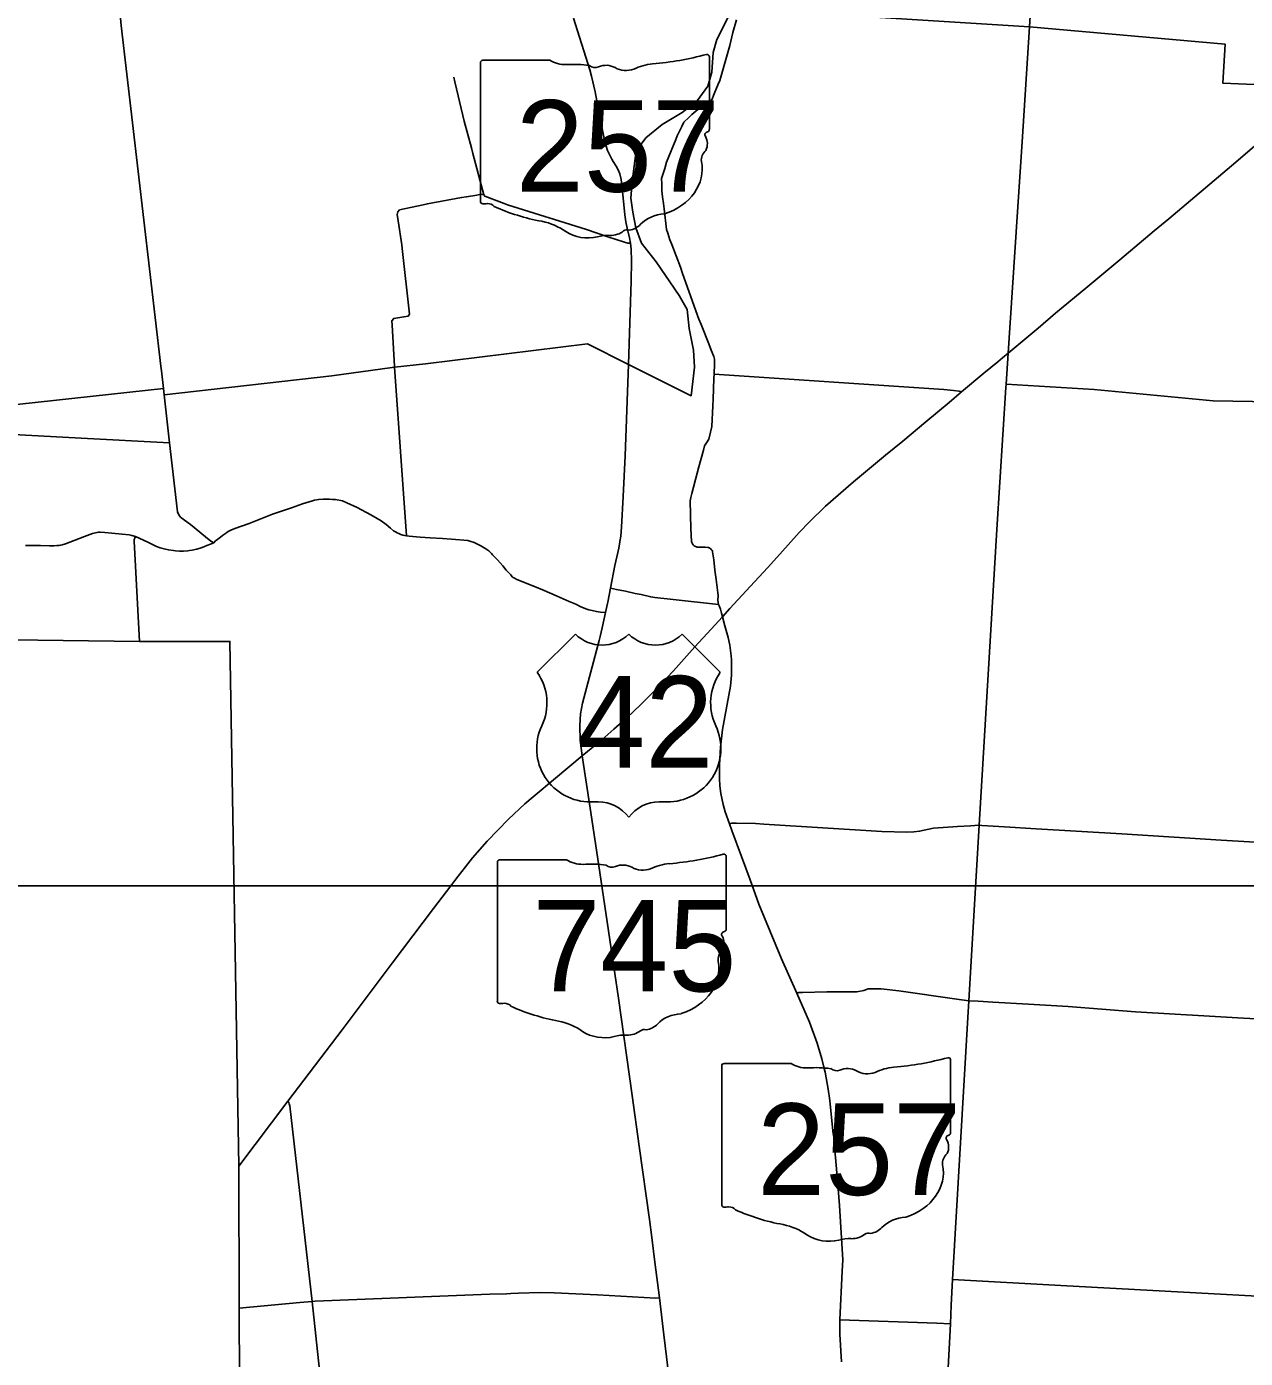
# Model space of a CAD drawing. Extents: x 1729596 to 1925846, y 659247 to 911751.
# Drawn here: x 1777664 to 1796200, y 807237 to 827504 of the extents above; entities that cross this region are included whole.
import ezdxf

# ---------------------------------------------------------------- set-up
doc = ezdxf.new("R2010")
doc.units = 0
for name, color, linetype in [('GM_X_County', 7, 'Continuous'), ('GM_X_County_Road', 7, 'Continuous'), ('GM_X_State_Route', 7, 'Continuous'), ('GM_X_State_Shield', 7, 'Continuous'), ('GM_X_Township', 7, 'Continuous'), ('GM_X_Township_Road', 7, 'Continuous'), ('GM_X_US_Route', 7, 'Continuous'), ('GM_X_US_Shield', 7, 'Continuous'), ('SH_Data', 7, 'Continuous')]:
    doc.layers.add(name, color=color, linetype=linetype)

msp = doc.modelspace()

# ---------------------------------------------------------------- linework, layer by layer
at = {"layer": 'GM_X_County'}
msp.add_lwpolyline([(1780927, 801312), (1780895, 808002), (1780889, 810163), (1780755, 818148), (1779378, 818146), (1775121, 818204)], dxfattribs=at)
at = {"layer": 'GM_X_County_Road'}
for points in [[(1792915, 827504), (1793116, 830642)], [(1792590, 822534), (1792728, 824607), (1792805, 825753), (1792915, 827502), (1792915, 827504)], [(1792558, 822011), (1792562, 822063), (1792590, 822534)], [(1791713, 807764), (1791713, 807764), (1791727, 808049), (1791747, 808435), (1791981, 812422), (1791996, 812680), (1792152, 815352), (1792421, 819851), (1792558, 822011)], [(1780612, 819735), (1780645, 819759), (1780686, 819790), (1780715, 819811), (1780738, 819826), (1780769, 819841), (1780828, 819865), (1781050, 819944), (1781402, 820082), (1781691, 820183), (1781861, 820241), (1782011, 820288), (1782042, 820296), (1782107, 820308), (1782172, 820313), (1782226, 820314), (1782272, 820313), (1782317, 820310), (1782363, 820305), (1782467, 820289), (1782536, 820259), (1782689, 820187), (1782899, 820076), (1782997, 820018), (1783056, 819981), (1783133, 819925), (1783197, 819870), (1783245, 819831), (1783272, 819816), (1783299, 819801), (1783327, 819788), (1783356, 819777), (1783385, 819767), (1783414, 819758), (1783439, 819754), (1783481, 819748), (1783650, 819735), (1783803, 819726), (1783988, 819713), (1784127, 819703), (1784372, 819682), (1784405, 819673), (1784469, 819651), (1784531, 819623), (1784574, 819600), (1784624, 819574), (1784647, 819559), (1784692, 819525), (1784732, 819486), (1784749, 819467), (1784825, 819388), (1784904, 819298), (1784959, 819231), (1785026, 819159), (1785050, 819133), (1785064, 819122), (1785094, 819104), (1785110, 819097), (1785248, 819040), (1785388, 818983), (1785533, 818924), (1785732, 818836), (1785914, 818757), (1786015, 818713), (1786091, 818676), (1786184, 818639), (1786216, 818628), (1786266, 818617), (1786329, 818603), (1786391, 818595), (1786468, 818586)], [(1777646, 819609), (1777873, 819605), (1778013, 819603), (1778079, 819603), (1778121, 819605), (1778161, 819608), (1778180, 819612), (1778205, 819618), (1778254, 819633), (1778388, 819686), (1778546, 819745), (1778668, 819790), (1778690, 819797), (1778713, 819802), (1778736, 819806), (1778759, 819808), (1778782, 819808), (1778853, 819805), (1778958, 819793), (1779119, 819779), (1779223, 819769), (1779266, 819761), (1779322, 819743), (1779440, 819691), (1779516, 819654)], [(1779516, 819654), (1779548, 819638), (1779641, 819594), (1779696, 819573), (1779754, 819555), (1779819, 819540), (1779897, 819529), (1779930, 819524), (1779991, 819521), (1780049, 819522), (1780114, 819528), (1780141, 819532), (1780183, 819537), (1780250, 819552), (1780319, 819573), (1780359, 819588), (1780402, 819606), (1780462, 819630), (1780509, 819649), (1780536, 819678), (1780571, 819703), (1780612, 819735)], [(1786546, 818956), (1786635, 818936), (1786770, 818912), (1786920, 818877), (1787011, 818860), (1787156, 818825), (1787219, 818816), (1787498, 818787), (1787499, 818787)], [(1787499, 818787), (1788188, 818712), (1788200, 818681), (1788215, 818640), (1788230, 818576), (1788246, 818524)], [(1782890, 800490), (1782881, 800644), (1782856, 800863), (1782676, 802437), (1782464, 804119), (1782395, 804661), (1782246, 805871), (1782006, 808105), (1781669, 811078), (1781659, 811109), (1781650, 811131), (1781636, 811151)], [(1791747, 808435), (1793395, 808348), (1794980, 808260), (1797031, 808146), (1797107, 808141), (1797153, 808138)], [(1780895, 808002), (1781819, 808088), (1782006, 808105), (1782052, 808109), (1784707, 808216), (1784962, 808220), (1785026, 808223), (1785143, 808231), (1785474, 808240), (1785685, 808234), (1786347, 808204), (1787231, 808155), (1787289, 808159)], [(1790033, 807825), (1791509, 807773), (1791713, 807764)], [(1791328, 800949), (1791359, 801588), (1791381, 801980), (1791400, 802336), (1791517, 804248), (1791555, 804839), (1791576, 805255), (1791663, 806861), (1791666, 806898), (1791673, 806996), (1791713, 807764)]]:
    msp.add_lwpolyline(points, dxfattribs=at)
at = {"layer": 'GM_X_State_Route'}
for points in [[(1786687, 819666), (1786699, 819749), (1786713, 819884), (1786736, 820353), (1786769, 820971), (1786817, 822362), (1786859, 823630), (1786863, 823932), (1786858, 824119), (1786848, 824207), (1786835, 824290), (1786796, 824437), (1786775, 824531), (1786760, 824638), (1786736, 824900), (1786705, 825179), (1786684, 825266), (1786661, 825325), (1786630, 825381), (1786584, 825450), (1786562, 825489), (1786529, 825557), (1786500, 825620), (1786459, 825751), (1786384, 826129), (1786309, 826513), (1786256, 826749), (1786229, 826847), (1785980, 827630)], [(1786502, 818744), (1786546, 818956), (1786609, 819304), (1786669, 819567), (1786687, 819663), (1786687, 819666)], [(1786385, 818223), (1786418, 818357), (1786468, 818586), (1786499, 818725), (1786502, 818744)], [(1788344, 817330), (1788369, 817465), (1788384, 817635), (1788386, 817682), (1788383, 817868), (1788379, 817929), (1788358, 818089), (1788333, 818205), (1788285, 818386), (1788246, 818524)], [(1786113, 816405), (1786081, 816641), (1786075, 816867), (1786090, 817045), (1786116, 817206), (1786370, 818161), (1786385, 818223)], [(1789933, 810648), (1789882, 811163), (1789857, 811335), (1789809, 811591), (1789782, 811691), (1789760, 811794), (1789687, 812036), (1789570, 812353), (1789380, 812793), (1789145, 813319), (1788800, 814150), (1788666, 814519), (1788535, 814873), (1788387, 815268), (1788352, 815370), (1788288, 815554), (1788258, 815665), (1788224, 815834), (1788209, 815948), (1788201, 816063), (1788201, 816122), (1788200, 816272), (1788218, 816541), (1788249, 816808), (1788344, 817330)], [(1787451, 806800), (1787357, 807594), (1787289, 808159), (1787220, 808700), (1787174, 809078), (1787137, 809350), (1786980, 810466), (1786873, 811238), (1786667, 812717), (1786361, 814768), (1786233, 815611), (1786113, 816405)], [(1789995, 809943), (1789934, 810642), (1789933, 810648)], [(1790058, 807184), (1790033, 807604), (1790033, 807825), (1790068, 808566), (1790079, 808738), (1790028, 809565), (1789995, 809943)]]:
    msp.add_lwpolyline(points, dxfattribs=at)
at = {"layer": 'GM_X_State_Shield'}
for p, q in [((1784567, 826956), (1784567, 824843)), ((1784567, 826956), (1784567, 824843)), ((1785621, 826993), (1784602, 826993)), ((1785621, 826993), (1784602, 826993)), ((1788048, 825939), (1788048, 827045)), ((1788048, 825939), (1788048, 827045)), ((1788047, 825940), (1788048, 825939)), ((1788047, 825940), (1788048, 825939)), ((1784823, 814786), (1784823, 812673)), ((1784823, 814786), (1784823, 812673)), ((1785876, 814822), (1784857, 814822)), ((1785876, 814822), (1784857, 814822)), ((1788303, 813769), (1788303, 814875)), ((1788303, 813769), (1788303, 814875)), ((1788303, 813769), (1788303, 813769)), ((1788303, 813769), (1788303, 813769)), ((1788237, 811688), (1788237, 809575)), ((1788237, 811688), (1788237, 809575)), ((1789291, 811725), (1788271, 811725)), ((1789291, 811725), (1788271, 811725)), ((1791717, 810671), (1791717, 811777)), ((1791717, 810671), (1791717, 811777)), ((1791717, 810672), (1791717, 810671)), ((1791717, 810672), (1791717, 810671))]:
    msp.add_line(p, q, dxfattribs=at)
for centre, major_axis, start_param, end_param in [((1786808, 829874), (3691, 0), 4.814394, 5.042369), ((1786808, 829874), (3691, 0), 4.814394, 5.042369), ((1788009, 827050), (38.7, 0), 6.141152, 7.989035), ((1788009, 827050), (38.7, 0), 6.141152, 7.989035), ((1784607, 826961), (40.3, 0), 1.712693, 3.28349), ((1784607, 826961), (40.3, 0), 1.712693, 3.28349), ((1785864, 827238), (391, 0), 4.042523, 4.731795), ((1785864, 827238), (391, 0), 4.042523, 4.731795), ((1785993, 825806), (1404, 0), 1.404758, 1.657858), ((1785993, 825806), (1404, 0), 1.404758, 1.657858), ((1786312, 826972), (113, 0), 3.836095, 5.185415), ((1786312, 826972), (113, 0), 3.836095, 5.185415), ((1786478, 826727), (235, 0), 0.950623, 2.079405), ((1786478, 826727), (235, 0), 0.950623, 2.079405), ((1786780, 827062), (282, 0), 4.081561, 5.145723), ((1786780, 827062), (282, 0), 4.081561, 5.145723), ((1787279, 826347), (743, 0), 1.699011, 2.107814), ((1787279, 826347), (743, 0), 1.699011, 2.107814), ((1788039, 825858), (60, 0), 1.883978, 3.671073), ((1788039, 825858), (60, 0), 1.883978, 3.671073), ((1788006, 825935), (41.5, 0), 5.05454, 6.418171), ((1788006, 825935), (41.5, 0), 5.05454, 6.418171), ((1787657, 825719), (360, 0), 5.934695, 6.695948), ((1787657, 825719), (360, 0), 5.934695, 6.695948), ((1787015, 825336), (923, 0), 5.101752, 6.440018), ((1787015, 825336), (923, 0), 5.101752, 6.440018), ((1788187, 825477), (262, 0), 2.387724, 3.262537), ((1788187, 825477), (262, 0), 2.387724, 3.262537), ((1784608, 824838), (40.7, 0), 3.00124, 4.508301), ((1784608, 824838), (40.7, 0), 3.00124, 4.508301), ((1784614, 825055), (310, 0), 4.665946, 4.897461), ((1784614, 825055), (310, 0), 4.665946, 4.897461), ((1784677, 824721), (112, 0), 0.519207, 1.627899), ((1784677, 824721), (112, 0), 0.519207, 1.627899), ((1786091, 826620), (2665, 0), 4.195997, 4.488961), ((1786091, 826620), (2665, 0), 4.195997, 4.488961), ((1787404, 824250), (506, 0), 1.647645, 2.488434), ((1787404, 824250), (506, 0), 1.647645, 2.488434), ((1785296, 823894), (834, 0), 0.823519, 1.323587), ((1785296, 823894), (834, 0), 0.823519, 1.323587), ((1786763, 824638), (298, 0), 4.937069, 5.64225), ((1786763, 824638), (298, 0), 4.937069, 5.64225), ((1786198, 824711), (529, 0), 4.026481, 4.996735), ((1786198, 824711), (529, 0), 4.026481, 4.996735), ((1786504, 823980), (435, 0), 1.495662, 1.94098), ((1786504, 823980), (435, 0), 1.495662, 1.94098), ((1786542, 824552), (282, 0), 4.691044, 5.507374), ((1786542, 824552), (282, 0), 4.691044, 5.507374), ((1786797, 824348), (79.4, 0), 1.147584, 2.315152), ((1786797, 824348), (79.4, 0), 1.147584, 2.315152), ((1784863, 814790), (40.3, 0), 1.712693, 3.28349), ((1784863, 814790), (40.3, 0), 1.712693, 3.28349), ((1786119, 815068), (391, 0), 4.042523, 4.731795), ((1786119, 815068), (391, 0), 4.042523, 4.731795), ((1786249, 813636), (1404, 0), 1.404758, 1.657858), ((1786249, 813636), (1404, 0), 1.404758, 1.657858), ((1786567, 814801), (113, 0), 3.836095, 5.185415), ((1786567, 814801), (113, 0), 3.836095, 5.185415), ((1786733, 814557), (235, 0), 0.950623, 2.079405), ((1786733, 814557), (235, 0), 0.950623, 2.079405), ((1787534, 814177), (743, 0), 1.699011, 2.107814), ((1787534, 814177), (743, 0), 1.699011, 2.107814), ((1787063, 817703), (3691, 0), 4.814394, 5.042369), ((1787063, 817703), (3691, 0), 4.814394, 5.042369), ((1788264, 814879), (38.7, 0), 6.141152, 7.989035), ((1788264, 814879), (38.7, 0), 6.141152, 7.989035), ((1787036, 814892), (282, 0), 4.081561, 5.145723), ((1787036, 814892), (282, 0), 4.081561, 5.145723), ((1788294, 813688), (60, 0), 1.883978, 3.671073), ((1788294, 813688), (60, 0), 1.883978, 3.671073), ((1788262, 813765), (41.5, 0), 5.05454, 6.418171), ((1788262, 813765), (41.5, 0), 5.05454, 6.418171), ((1787913, 813548), (360, 0), 5.934695, 6.695948), ((1787913, 813548), (360, 0), 5.934695, 6.695948), ((1788442, 813306), (262, 0), 2.387724, 3.262537), ((1788442, 813306), (262, 0), 2.387724, 3.262537), ((1787270, 813166), (923, 0), 5.101752, 6.440018), ((1787270, 813166), (923, 0), 5.101752, 6.440018), ((1784863, 812668), (40.7, 0), 3.00124, 4.508301), ((1784863, 812668), (40.7, 0), 3.00124, 4.508301), ((1784869, 812884), (310, 0), 4.665946, 4.897461), ((1784869, 812884), (310, 0), 4.665946, 4.897461), ((1784933, 812551), (112, 0), 0.519207, 1.627899), ((1784933, 812551), (112, 0), 0.519207, 1.627899), ((1786346, 814449), (2665, 0), 4.195997, 4.488961), ((1786346, 814449), (2665, 0), 4.195997, 4.488961), ((1787659, 812079), (506, 0), 1.647645, 2.488434), ((1787659, 812079), (506, 0), 1.647645, 2.488434), ((1785551, 811723), (834, 0), 0.823519, 1.323587), ((1785551, 811723), (834, 0), 0.823519, 1.323587), ((1787019, 812468), (298, 0), 4.937069, 5.64225), ((1787019, 812468), (298, 0), 4.937069, 5.64225), ((1786453, 812540), (529, 0), 4.026481, 4.996735), ((1786453, 812540), (529, 0), 4.026481, 4.996735), ((1786759, 811810), (435, 0), 1.495662, 1.94098), ((1786759, 811810), (435, 0), 1.495662, 1.94098), ((1786797, 812382), (282, 0), 4.691044, 5.507374), ((1786797, 812382), (282, 0), 4.691044, 5.507374), ((1787053, 812177), (79.4, 0), 1.147584, 2.315152), ((1787053, 812177), (79.4, 0), 1.147584, 2.315152), ((1788277, 811693), (40.3, 0), 1.712693, 3.28349), ((1788277, 811693), (40.3, 0), 1.712693, 3.28349), ((1789533, 811970), (391, 0), 4.042523, 4.731795), ((1789533, 811970), (391, 0), 4.042523, 4.731795), ((1790478, 814606), (3691, 0), 4.814394, 5.042369), ((1790478, 814606), (3691, 0), 4.814394, 5.042369), ((1791679, 811782), (38.7, 0), 6.141152, 7.989035), ((1791679, 811782), (38.7, 0), 6.141152, 7.989035), ((1789663, 810538), (1404, 0), 1.404758, 1.657858), ((1789663, 810538), (1404, 0), 1.404758, 1.657858), ((1789982, 811704), (113, 0), 3.836095, 5.185415), ((1789982, 811704), (113, 0), 3.836095, 5.185415), ((1790147, 811459), (235, 0), 0.950623, 2.079405), ((1790147, 811459), (235, 0), 0.950623, 2.079405), ((1790450, 811794), (282, 0), 4.081561, 5.145723), ((1790450, 811794), (282, 0), 4.081561, 5.145723), ((1790948, 811079), (743, 0), 1.699011, 2.107814), ((1790948, 811079), (743, 0), 1.699011, 2.107814), ((1791676, 810667), (41.5, 0), 5.05454, 6.418171), ((1791676, 810667), (41.5, 0), 5.05454, 6.418171), ((1791708, 810590), (60, 0), 1.883978, 3.671073), ((1791708, 810590), (60, 0), 1.883978, 3.671073), ((1791327, 810451), (360, 0), 5.934695, 6.695948), ((1791327, 810451), (360, 0), 5.934695, 6.695948), ((1791856, 810209), (262, 0), 2.387724, 3.262537), ((1791856, 810209), (262, 0), 2.387724, 3.262537), ((1790684, 810068), (923, 0), 5.101752, 6.440018), ((1790684, 810068), (923, 0), 5.101752, 6.440018), ((1788277, 809570), (40.7, 0), 3.00124, 4.508301), ((1788277, 809570), (40.7, 0), 3.00124, 4.508301), ((1788283, 809787), (310, 0), 4.665946, 4.897461), ((1788283, 809787), (310, 0), 4.665946, 4.897461), ((1788347, 809453), (112, 0), 0.519207, 1.627899), ((1788347, 809453), (112, 0), 0.519207, 1.627899), ((1789760, 811352), (2665, 0), 4.195997, 4.488961), ((1789760, 811352), (2665, 0), 4.195997, 4.488961), ((1788965, 808626), (834, 0), 0.823519, 1.323587), ((1788965, 808626), (834, 0), 0.823519, 1.323587), ((1791074, 808982), (506, 0), 1.647645, 2.488434), ((1791074, 808982), (506, 0), 1.647645, 2.488434), ((1789867, 809443), (529, 0), 4.026481, 4.996735), ((1789867, 809443), (529, 0), 4.026481, 4.996735), ((1790173, 808712), (435, 0), 1.495662, 1.94098), ((1790173, 808712), (435, 0), 1.495662, 1.94098), ((1790212, 809284), (282, 0), 4.691044, 5.507374), ((1790212, 809284), (282, 0), 4.691044, 5.507374), ((1790467, 809080), (79.4, 0), 1.147584, 2.315152), ((1790467, 809080), (79.4, 0), 1.147584, 2.315152), ((1790433, 809370), (298, 0), 4.937069, 5.64225), ((1790433, 809370), (298, 0), 4.937069, 5.64225)]:
    msp.add_ellipse(centre, major_axis=major_axis, ratio=0.8, start_param=start_param, end_param=end_param, dxfattribs=at)
at = {"layer": 'GM_X_Township'}
for points in [[(1792915, 827502), (1793120, 830695), (1793232, 832236), (1793303, 833333), (1793352, 834099), (1793647, 838152), (1793839, 840685)], [(1777282, 821728), (1779745, 821996), (1779756, 821898), (1782305, 822188), (1783225, 822317), (1783260, 822320), (1783730, 822371), (1786192, 822674), (1786817, 822362), (1787772, 821886), (1787820, 822322), (1787807, 822581), (1787740, 822908), (1787709, 823197), (1787588, 823413), (1787237, 823925), (1787015, 824208), (1786931, 824440), (1786884, 824679), (1786853, 824895), (1786873, 825147), (1786934, 825612), (1787079, 825811), (1787332, 826016), (1787635, 826195), (1787864, 826374), (1788025, 826596), (1788083, 826812), (1788106, 827111), (1788160, 827310), (1788402, 827781)], [(1788529, 827772), (1792915, 827502), (1795894, 827235), (1795858, 826641), (1797406, 826576), (1797648, 826566), (1797538, 824584), (1797542, 824510), (1797556, 824405), (1797555, 824304), (1797417, 821763), (1797960, 821729), (1797746, 818394), (1797534, 815021), (1797366, 812352), (1797107, 808141), (1796898, 804715)]]:
    msp.add_lwpolyline(points, dxfattribs=at)
at = {"layer": 'GM_X_Township_Road'}
for points in [[(1779744, 821999), (1779714, 822265), (1779706, 822335), (1779104, 827522), (1779067, 827919), (1778790, 830773), (1778783, 830840), (1778783, 830969), (1778793, 830993), (1778833, 831011), (1778991, 831022), (1779061, 831027), (1779089, 831037), (1779109, 831077), (1779069, 831445), (1779061, 831516), (1778972, 832053), (1778950, 832222), (1778909, 832522)], [(1788120, 822216), (1788120, 822216), (1788126, 822374), (1788128, 822441), (1788118, 822483), (1788077, 822580), (1788038, 822675), (1787922, 822970), (1787889, 823052), (1787640, 823748), (1787607, 823843), (1787475, 824188), (1787448, 824260), (1787416, 824361), (1787398, 824415), (1787361, 824729), (1787352, 824812), (1787337, 824916), (1787324, 825006), (1787323, 825112), (1787322, 825191), (1787368, 825343), (1787398, 825442), (1787537, 825784), (1787560, 825841), (1787628, 825984), (1787658, 826050), (1787734, 826123), (1787781, 826168), (1787903, 826268), (1787957, 826313), (1788002, 826340), (1788083, 826391), (1788119, 826483), (1788184, 826628), (1788209, 826684), (1788361, 827216), (1788405, 827412), (1788461, 827606)], [(1784618, 824946), (1784452, 825573), (1784431, 825658), (1784320, 826065), (1784297, 826149), (1784176, 826663), (1784159, 826737)], [(1783259, 822338), (1783221, 822958), (1783217, 823026), (1783247, 823062), (1783403, 823087), (1783468, 823098), (1783486, 823128), (1783376, 824125), (1783369, 824183), (1783314, 824549), (1783299, 824645), (1783309, 824683), (1783335, 824717), (1783697, 824794), (1783760, 824807), (1784280, 824902), (1784353, 824916), (1784510, 824941), (1784574, 824952), (1784618, 824946), (1784632, 824924), (1784929, 824812), (1784979, 824793), (1786179, 824415), (1786504, 824307), (1786757, 824225), (1786806, 824209), (1786824, 824206), (1786848, 824207)], [(1783439, 819754), (1783260, 822320), (1783259, 822338)], [(1788188, 818712), (1788180, 818740), (1788177, 818778), (1788179, 818842), (1788175, 818887), (1788149, 819089), (1788131, 819232), (1788115, 819387), (1788096, 819509), (1788093, 819519), (1788088, 819530), (1788082, 819541), (1788074, 819550), (1788065, 819559), (1788056, 819566), (1788045, 819572), (1788034, 819576), (1788022, 819579), (1787982, 819582), (1787863, 819584), (1787850, 819586), (1787838, 819590), (1787827, 819596), (1787817, 819603), (1787807, 819611), (1787799, 819620), (1787791, 819631), (1787786, 819642), (1787781, 819654), (1787778, 819666), (1787768, 819865), (1787757, 820287), (1787767, 820339), (1787779, 820400), (1787861, 820706), (1787888, 820806), (1787956, 821060), (1787974, 821125), (1788006, 821169), (1788040, 821227), (1788064, 821330), (1788084, 821417), (1788101, 821734), (1788106, 821833), (1788117, 822149), (1788120, 822216)], [(1788120, 822216), (1791616, 821980), (1791759, 821967), (1791848, 821957), (1791884, 821945)], [(1792562, 822063), (1793900, 821979), (1795708, 821807), (1796906, 821790), (1797417, 821763)], [(1779839, 821168), (1779756, 821898), (1779745, 821996), (1779744, 821999)], [(1777369, 821317), (1777379, 821311), (1777403, 821302), (1777475, 821295), (1777649, 821286), (1777837, 821276), (1778492, 821239), (1779839, 821168), (1779960, 820119), (1779977, 820076), (1780006, 820041), (1780064, 819993), (1780157, 819926), (1780385, 819739), (1780466, 819673), (1780509, 819649)], [(1779378, 818146), (1779297, 819671), (1779298, 819684), (1779301, 819697), (1779305, 819710), (1779309, 819719), (1779322, 819743)], [(1788352, 815370), (1788390, 815380), (1788460, 815383), (1788748, 815375), (1788877, 815369), (1790669, 815254), (1791049, 815244), (1791157, 815250), (1791245, 815260), (1791457, 815304), (1791820, 815329), (1792020, 815342), (1792152, 815352)], [(1792152, 815352), (1792194, 815348), (1792538, 815327), (1793017, 815298), (1794320, 815218), (1795831, 815124), (1797378, 815030)], [(1789380, 812793), (1789410, 812804), (1789463, 812806), (1789834, 812813), (1790208, 812814), (1790288, 812815), (1790397, 812833), (1790463, 812859), (1790661, 812863), (1790931, 812830), (1791812, 812705), (1791996, 812680)], [(1791996, 812680), (1792135, 812671), (1792361, 812658), (1792900, 812626), (1793503, 812590), (1794528, 812511), (1796172, 812413), (1797338, 812354)]]:
    msp.add_lwpolyline(points, dxfattribs=at)
at = {"layer": 'GM_X_US_Route'}
for points in [[(1792508, 822464), (1792590, 822534), (1793050, 822917), (1793314, 823141), (1793805, 823550), (1794289, 823956), (1794815, 824398), (1795038, 824581), (1795987, 825387), (1796517, 825835), (1796631, 825927), (1796695, 825983)], [(1780889, 810163), (1781636, 811151), (1782464, 812239), (1783225, 813253), (1783854, 814085), (1784048, 814342), (1784229, 814573), (1784341, 814717), (1784446, 814854), (1784670, 815110), (1784992, 815444), (1785243, 815676), (1785368, 815784), (1785705, 816066), (1786113, 816405), (1786413, 816648), (1786595, 816812), (1786790, 816985), (1786998, 817182), (1787210, 817389), (1787502, 817701), (1787826, 818063), (1788077, 818333), (1788246, 818524), (1788360, 818647), (1788609, 818917), (1788930, 819268), (1789118, 819475), (1789413, 819805), (1789572, 819966), (1789812, 820205), (1790241, 820577), (1790726, 820980), (1790989, 821194), (1791340, 821489), (1791695, 821786), (1791884, 821945), (1792222, 822228), (1792434, 822401), (1792508, 822464)]]:
    msp.add_lwpolyline(points, dxfattribs=at)
at = {"layer": 'GM_X_US_Shield'}
for p, q in [((1786010, 818258), (1785430, 817678)), ((1786010, 818258), (1785430, 817678)), ((1788214, 817678), (1787634, 818258)), ((1788214, 817678), (1787634, 818258)), ((1786242, 815706), (1786358, 815706)), ((1786242, 815706), (1786358, 815706)), ((1787286, 815706), (1787402, 815706)), ((1787286, 815706), (1787402, 815706))]:
    msp.add_line(p, q, dxfattribs=at)
for centre, radius, start, end in [((1786416, 818672), 580, 225.573, 314.427), ((1786416, 818672), 580, 225.573, 314.427), ((1787228, 818672), 580, 225.573, 314.427), ((1787228, 818672), 580, 225.573, 314.427), ((1784765, 817212), 812, 334.5471, 35.0009), ((1784765, 817212), 812, 334.5471, 35.0009), ((1788879, 817212), 812, 144.9991, 205.4529), ((1788879, 817212), 812, 144.9991, 205.4529), ((1786233, 816518), 812, 154.8319, 270.6383), ((1786233, 816518), 812, 154.8319, 270.6383), ((1787411, 816518), 812, 269.3617, 25.1681), ((1787411, 816518), 812, 269.3617, 25.1681), ((1786358, 815126), 580, 36.8699, 90), ((1786358, 815126), 580, 36.8699, 90), ((1787286, 815126), 580, 90, 143.1301), ((1787286, 815126), 580, 90, 143.1301)]:
    msp.add_arc(centre, radius, start, end, dxfattribs=at)
at = {"layer": 'SH_Data'}
msp.add_line((1828599, 814428), (1752099, 814428), dxfattribs=at)

# ---------------------------------------------------------------- texts
at = {"layer": 'GM_X_State_Shield'}
for s, p in [('257', (1785103, 824992)), ('257', (1785103, 824992)), ('745', (1785354, 812822)), ('745', (1785354, 812822)), ('257', (1788773, 809724)), ('257', (1788773, 809724))]:
    msp.add_text(s, height=1392.2, dxfattribs=at).set_placement(p)
at = {"layer": 'GM_X_US_Shield'}
msp.add_text('42', height=1392.2, dxfattribs=at).set_placement((1786038, 816228))
msp.add_text('42', height=1392.2, dxfattribs=at).set_placement((1786038, 816228))

doc.saveas('drawing.dxf')
